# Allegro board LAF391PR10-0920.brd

Outline 301.1 x 113.1 mm; copper layers: TOP, GND1, IN1, GND2, IN2, IN3, VCC, IN4, GND3, BOTTOM. Coordinates in mm from the lower left corner of the outline.

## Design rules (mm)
net group BC: nets BC_CLK_ECE1117 BC_DAT_ECE1117
net group CPU_DP3_AUXN: nets CPU_DP3_AUXN CPU_DP3_AUXP
net group DP4: nets VCC_GT_SENSE VSS_GT_SENSE
net group DP5: nets VCCIO_SENSE VSSIO_SENSE
net group DP6: nets VCCSENSE VSSSENSE
net group PCIE_PRX_C_DTX_N4: nets PCIE_PRX_C_DTX_N4 PCIE_PRX_DTX_N4
net group PCIE_PRX_C_DTX_P4: nets PCIE_PRX_C_DTX_P4 PCIE_PRX_DTX_P4
net group PCIE_PTX_C_DRX_N4: nets PCIE_PTX_C_DRX_N4 PCIE_PTX_DRX_N4
net group PCIE_PTX_C_DRX_P4: nets PCIE_PTX_C_DRX_P4 PCIE_PTX_DRX_P4
net group PECI: nets PECI_EC PECI_EC_R
net group USB3_PRX_C_DTX_N1: nets USB3_PRX_C_DTX_N1 USB3_PRX_DTX_N1
net group USB3_PRX_C_DTX_P1: nets USB3_PRX_C_DTX_P1 USB3_PRX_DTX_P1
net group ASYNCHRONOUS: nets +DDR_VREF_A_CA +DDR_VREF_A_DQ +DDR_VREF_B_CA +DDR_VREF_B_DQ +DDR_VREF_CA CFG_RCOMP CPU_POPIRCOMP DDR_DRAMRST#_R EDP_COMP EDRAM_OPIO_RCOMP EMMC_RCOMP EOPIO_RCOMP H_CATERR# H_THERMTRIP# H_VCCST_PWRGD_XDP PCH_PLTRST# PCH_PLTRST#_5105 PCH_PLTRST#_AND PCH_PLTRST#_EC PCH_POPIRCOMP PCIE_RCOMPN PCIE_RCOMPP PLTRST_LAN# PLTRST_TPM# SD_RCOMP SM_RCOMP0 SM_RCOMP1 SM_RCOMP2 USBCOMP VCCST_PWRGD VCCST_PWRGD_CPU VCCST_PWRGD_EC XDP_OBS0 XDP_OBS0_R XDP_OBS1 XDP_OBS1_R XDP_OBS2_R XDP_OBS3_R
net group CARD READER: nets SD/MMCCD# SD/MMCCLK SD/MMCCLK_R SD/MMCCMD SD/MMCCMD_R SD/MMCDAT0/RCLK+ SD/MMCDAT0/RCLK+_R SD/MMCDAT1/RCLK- SD/MMCDAT1/RCLK-_R SD/MMCDAT2 SD/MMCDAT2_R SD/MMCDAT3 SD/MMCDAT3_R SD_UHS2_D0N SD_UHS2_D0P SD_UHS2_D1N SD_UHS2_D1P SDWP
net group CL_IAMT: nets PCH_CL_CLK1 PCH_CL_DATA1 PCH_CL_RST1#
net group CLK: nets CLKDET# CPU_XDP_TCLK DAT_TP_SIO_I2C_CLK JTAG_CLK MEC_XTAL1 MEC_XTAL2 MEC_XTAL2_R MSCLK PCH_JTAG_TCK PCI_CLK_LPC1 TBTA_ROM_CLK_PD_R UPD1_SMBCLK UPD1_SMBCLK_Q UPD2_SMBCLK XTALI XTALO XTALO_R
net group CODEC: nets +MIC2-VREFO-L +MIC2-VREFO-R AUD_HP_NB_SENSE AUD_HP_OUT_L AUD_HP_OUT_L1 AUD_HP_OUT_R AUD_HP_OUT_R1 AUD_SENSE_A HP_OUT_L HP_OUT_R INT_SPK_L+ INT_SPK_L- INT_SPK_R+ INT_SPK_R- INT_SPKR_L+ INT_SPKR_L- INT_SPKR_R+ INT_SPKR_R- RING2 RING2_R SLEEVE SLEEVE_R
net group CRITICAL: nets H_CPUPWRGD INTRUDER# PCH_DPWROK PCH_DPWROK_EC PCH_PCIE_WAKE# PCH_RSMRST# PCH_RSMRST#_AND PCH_RTCRST# PCIE_WAKE# PCIE_WAKE#_R RESET_OUT#_R SIO_PWRBTN# SIO_SLP_A# SRTCRST# SYS_PWROK SYS_RESET# SYS_RESET#_R XDP_DBRESET#
net group CRT: nets BLUE BLUE_CRT CLK_DDC2_CRT DAT_DDC2_CRT GREEN GREEN_CRT HSYNC_CONN HSYNC_CRT RED RED_CRT VSYNC_CONN VSYNC_CRT
net group DDR-DQS: nets DDR_A_DQS0 DDR_A_DQS1 DDR_A_DQS2 DDR_A_DQS3 DDR_A_DQS4 DDR_A_DQS5 DDR_A_DQS6 DDR_A_DQS7 DDR_A_DQS#0 DDR_A_DQS#1 DDR_A_DQS#2 DDR_A_DQS#3 DDR_A_DQS#4 DDR_A_DQS#5 DDR_A_DQS#6 DDR_A_DQS#7 DDR_B_DQS0 DDR_B_DQS1 DDR_B_DQS2 DDR_B_DQS3 DDR_B_DQS4 DDR_B_DQS5 DDR_B_DQS6 DDR_B_DQS7 DDR_B_DQS#0 DDR_B_DQS#1 DDR_B_DQS#2 DDR_B_DQS#3 DDR_B_DQS#4 DDR_B_DQS#5 DDR_B_DQS#6 DDR_B_DQS#7
net group DDRA-ALERT: nets DDR_A_ALERT#
net group DDRA-CKE: nets DDR_A_CKE0 DDR_A_CKE1 DDR_A_CKE2 DDR_A_CKE3
net group DDRA-CLK: nets DDR_A_CLK0 DDR_A_CLK1 DDR_A_CLK#0 DDR_A_CLK#1
net group DDRA-CTL: nets DDR_A_CS#0 DDR_A_CS#1 DDR_A_ODT0 DDR_A_ODT1
net group DDRA-D0: nets DDR_A_D0 DDR_A_D1 DDR_A_D2 DDR_A_D3 DDR_A_D4 DDR_A_D5 DDR_A_D6 DDR_A_D7
net group DDRA-D1: nets DDR_A_D8 DDR_A_D9 DDR_A_D10 DDR_A_D11 DDR_A_D12 DDR_A_D13 DDR_A_D14 DDR_A_D15
net group DDRA-D2: nets DDR_A_D16 DDR_A_D17 DDR_A_D18 DDR_A_D19 DDR_A_D20 DDR_A_D21 DDR_A_D22 DDR_A_D23
net group DDRA-D3: nets DDR_A_D24 DDR_A_D25 DDR_A_D26 DDR_A_D27 DDR_A_D28 DDR_A_D29 DDR_A_D30 DDR_A_D31
net group DDRA-D4: nets DDR_A_D32 DDR_A_D33 DDR_A_D34 DDR_A_D35 DDR_A_D36 DDR_A_D37 DDR_A_D38 DDR_A_D39
net group DDRA-D5: nets DDR_A_D40 DDR_A_D41 DDR_A_D42 DDR_A_D43 DDR_A_D44 DDR_A_D45 DDR_A_D46 DDR_A_D47
net group DDRA-D6: nets DDR_A_D48 DDR_A_D49 DDR_A_D50 DDR_A_D51 DDR_A_D52 DDR_A_D53 DDR_A_D54 DDR_A_D55
net group DDRA-D7: nets DDR_A_D56 DDR_A_D57 DDR_A_D58 DDR_A_D59 DDR_A_D60 DDR_A_D61 DDR_A_D62 DDR_A_D63
net group DDRA-MA: nets DDR_A_ACT# DDR_A_BA0 DDR_A_BA1 DDR_A_BG0 DDR_A_BG1 DDR_A_MA0 DDR_A_MA1 DDR_A_MA2 DDR_A_MA3 DDR_A_MA4 DDR_A_MA5 DDR_A_MA6 DDR_A_MA7 DDR_A_MA8 DDR_A_MA9 DDR_A_MA10 DDR_A_MA11 DDR_A_MA12 DDR_A_MA13 DDR_A_MA14 DDR_A_MA15 DDR_A_MA16 DDR_A_PARITY
net group DDRB-ALERT: nets DDR_B_ALERT#
net group DDRB-CKE: nets DDR_B_CKE0 DDR_B_CKE1 DDR_B_CKE2 DDR_B_CKE3
net group DDRB-CLK: nets DDR_B_CLK0 DDR_B_CLK1 DDR_B_CLK#0 DDR_B_CLK#1
net group DDRB-CTL: nets DDR_B_CS#0 DDR_B_CS#1 DDR_B_ODT0 DDR_B_ODT1
net group DDRB-D0: nets DDR_B_D0 DDR_B_D1 DDR_B_D2 DDR_B_D3 DDR_B_D4 DDR_B_D5 DDR_B_D6 DDR_B_D7
net group DDRB-D1: nets DDR_B_D8 DDR_B_D9 DDR_B_D10 DDR_B_D11 DDR_B_D12 DDR_B_D13 DDR_B_D14 DDR_B_D15
net group DDRB-D2: nets DDR_B_D16 DDR_B_D17 DDR_B_D18 DDR_B_D19 DDR_B_D20 DDR_B_D21 DDR_B_D22 DDR_B_D23
net group DDRB-D3: nets DDR_B_D24 DDR_B_D25 DDR_B_D26 DDR_B_D27 DDR_B_D28 DDR_B_D29 DDR_B_D30 DDR_B_D31
net group DDRB-D4: nets DDR_B_D32 DDR_B_D33 DDR_B_D34 DDR_B_D35 DDR_B_D36 DDR_B_D37 DDR_B_D38 DDR_B_D39
net group DDRB-D5: nets DDR_B_D40 DDR_B_D41 DDR_B_D42 DDR_B_D43 DDR_B_D44 DDR_B_D45 DDR_B_D46 DDR_B_D47
net group DDRB-D6: nets DDR_B_D48 DDR_B_D49 DDR_B_D50 DDR_B_D51 DDR_B_D52 DDR_B_D53 DDR_B_D54 DDR_B_D55
net group DDRB-D7: nets DDR_B_D56 DDR_B_D57 DDR_B_D58 DDR_B_D59 DDR_B_D60 DDR_B_D61 DDR_B_D62 DDR_B_D63
net group DDRB-MA: nets DDR_B_ACT# DDR_B_BA0 DDR_B_BA1 DDR_B_BG0 DDR_B_BG1 DDR_B_MA0 DDR_B_MA1 DDR_B_MA2 DDR_B_MA3 DDR_B_MA4 DDR_B_MA5 DDR_B_MA6 DDR_B_MA7 DDR_B_MA8 DDR_B_MA9 DDR_B_MA10 DDR_B_MA11 DDR_B_MA12 DDR_B_MA13 DDR_B_MA14 DDR_B_MA15 DDR_B_MA16 DDR_B_PARITY
net group DP: nets CPU_DP2_AUXN CPU_DP2_AUXN_C CPU_DP2_AUXP CPU_DP2_AUXP_C CPU_DP2_N0 CPU_DP2_N0_C CPU_DP2_N1 CPU_DP2_N1_C CPU_DP2_N2 CPU_DP2_N2_C CPU_DP2_N3 CPU_DP2_N3_C CPU_DP2_P0 CPU_DP2_P0_C CPU_DP2_P1 CPU_DP2_P1_C CPU_DP2_P2 CPU_DP2_P2_C CPU_DP2_P3 CPU_DP2_P3_C SW2_DP1_AUXN SW2_DP1_AUXN_C SW2_DP1_AUXP SW2_DP1_AUXP_C SW2_DP1_N0 SW2_DP1_N0_C SW2_DP1_N1 SW2_DP1_N1_C SW2_DP1_N2 SW2_DP1_N2_C SW2_DP1_N3 SW2_DP1_N3_C SW2_DP1_P0 SW2_DP1_P0_C SW2_DP1_P1 SW2_DP1_P1_C SW2_DP1_P2 SW2_DP1_P2_C SW2_DP1_P3 SW2_DP1_P3_C SW2_DP3_AUXN SW2_DP3_AUXN_C SW2_DP3_AUXP SW2_DP3_AUXP_C SW2_DP3_N0 SW2_DP3_N0_C SW2_DP3_N1 SW2_DP3_N1_C SW2_DP3_P0 SW2_DP3_P0_C SW2_DP3_P1 SW2_DP3_P1_C TBTA_AUXN_C
net group DP1.3: nets TBTA_RX1N TBTA_RX1P TBTA_RX2N TBTA_RX2P TBTA_SBU1 TBTA_SBU1_R TBTA_SBU2 TBTA_SBU2_R TBTA_TX1N TBTA_TX1N_C TBTA_TX1P TBTA_TX1P_C TBTA_TX2N TBTA_TX2N_C TBTA_TX2P TBTA_TX2P_C TUSB546A_SBU1_R TUSB546A_SBU2_R
net group EDP: nets EDP_AUXN EDP_AUXN_C EDP_AUXP EDP_AUXP_C EDP_TXN0 EDP_TXN0_C EDP_TXN1 EDP_TXN1_C EDP_TXP0 EDP_TXP0_C EDP_TXP1 EDP_TXP1_C
net group EMI: nets BIA_PWM BIA_PWM_EC BST_3V BST_5V CLKRUN# EDP_BIA_PWM HOST_DEBUG_TX M_ID2# TP_LAN_JTAG_TCK
net group ESD-GND: nets CPU_XDP_PRDY# CPU_XDP_PREQ# CPU_XDP_TDI CPU_XDP_TDO CPU_XDP_TMS CPU_XDP_TRST# PCH_JTAG_TDI PCH_JTAG_TDO PCH_JTAG_TMS PCH_PWROK POWER_SW#_MB POWER_SW_IN# TDI_XDP TDO_XDP TRST#_XDP XDP_JTAGX XDP_TMS
net group ESD-NOCROSS-MOAT: nets CFG0 CFG1 CFG2 CFG3 CFG4 CFG5 CFG6 CFG7 CFG8 CFG9 CFG10 CFG11 CFG12 CFG13 CFG14 CFG15 CFG16 CFG17 CFG18 CFG19 JTAG_RST# JTAG_TDI JTAG_TDO ME_SUS_PWR_ACK RUNPWROK SIO_EXT_SMI# SIO_SLP_S0# SIO_SLP_S3# SIO_SLP_S4# SIO_SLP_S5# SUSACK# USB_OC0# USB_OC1# USB_OC2# USB_OC3#
net group HDA: nets DMIC0 DMIC_CLK0 HDA_BIT_CLK HDA_BIT_CLK_R HDA_RST# HDA_SDIN0_R HDA_SDOUT HDA_SYNC
net group HDMI: nets CPU_DP1_AUXN CPU_DP1_AUXP CPU_DP1_CTRL_CLK CPU_DP1_CTRL_DATA CPU_DP1_N0 CPU_DP1_N1 CPU_DP1_N2 CPU_DP1_N3 CPU_DP1_P0 CPU_DP1_P1 CPU_DP1_P2 CPU_DP1_P3 HDMI_CLKN HDMI_CLKP HDMI_L_CLKN HDMI_L_CLKP HDMI_L_TX_N0 HDMI_L_TX_N1 HDMI_L_TX_N2 HDMI_L_TX_P0 HDMI_L_TX_P1 HDMI_L_TX_P2 HDMI_TX_N0 HDMI_TX_N1 HDMI_TX_N2 HDMI_TX_P0 HDMI_TX_P1 HDMI_TX_P2
net group I2C: nets ISH_I2C2_SCL ISH_I2C2_SCL_R ISH_I2C2_SDA ISH_I2C2_SDA_R
net group MDI: nets LAN_MDIN0 LAN_MDIN0_L LAN_MDIN1 LAN_MDIN1_L LAN_MDIN2 LAN_MDIN2_L LAN_MDIN3 LAN_MDIN3_L LAN_MDIP0 LAN_MDIP0_L LAN_MDIP1 LAN_MDIP1_L LAN_MDIP2 LAN_MDIP2_L LAN_MDIP3 LAN_MDIP3_L
net group MDI-CONN: nets RJ45_MDIN0 RJ45_MDIN1 RJ45_MDIN2 RJ45_MDIN3 RJ45_MDIP0 RJ45_MDIP1 RJ45_MDIP2 RJ45_MDIP3
net group OTHER-SINGLE: nets BAT1_LED# BAT2_LED# BATT_WHITE# BATT_YELLOW#
net group PCIE: nets PCIE_PRX_C_DTX_N1 PCIE_PRX_C_DTX_N11 PCIE_PRX_C_DTX_N12 PCIE_PRX_C_DTX_P1 PCIE_PRX_C_DTX_P11 PCIE_PRX_C_DTX_P12 PCIE_PRX_C_RD_DTX_N11 PCIE_PRX_C_RD_DTX_N12 PCIE_PRX_C_RD_DTX_P11 PCIE_PRX_C_RD_DTX_P12 PCIE_PRX_DTX_N1 PCIE_PRX_DTX_N3 PCIE_PRX_DTX_N11 PCIE_PRX_DTX_N12 PCIE_PRX_DTX_P1 PCIE_PRX_DTX_P3 PCIE_PRX_DTX_P11 PCIE_PRX_DTX_P12 PCIE_PRX_RD_DTX_N11 PCIE_PRX_RD_DTX_N12 PCIE_PRX_RD_DTX_P11 PCIE_PRX_RD_DTX_P12 PCIE_PTX_C_DRX_N1 PCIE_PTX_C_DRX_N3 PCIE_PTX_C_DRX_N11 PCIE_PTX_C_DRX_N12 PCIE_PTX_C_DRX_P1 PCIE_PTX_C_DRX_P3 PCIE_PTX_C_DRX_P11 PCIE_PTX_C_DRX_P12 PCIE_PTX_C_RD_DRX_N11 PCIE_PTX_C_RD_DRX_N12 PCIE_PTX_C_RD_DRX_P11 PCIE_PTX_C_RD_DRX_P12 PCIE_PTX_DRX_N1 PCIE_PTX_DRX_N3 PCIE_PTX_DRX_N11 PCIE_PTX_DRX_N12 PCIE_PTX_DRX_P1 PCIE_PTX_DRX_P3 PCIE_PTX_DRX_P11 PCIE_PTX_DRX_P12 PCIE_PTX_RD_DRX_N11 PCIE_PTX_RD_DRX_N12 PCIE_PTX_RD_DRX_P11 PCIE_PTX_RD_DRX_P12
net group PLATFORM CLK: nets CLK_ITPXDP_N CLK_ITPXDP_N_R CLK_ITPXDP_P CLK_ITPXDP_P_R CLK_PCIE_N0 CLK_PCIE_N1 CLK_PCIE_N3 CLK_PCIE_N4 CLK_PCIE_N5 CLK_PCIE_P0 CLK_PCIE_P1 CLK_PCIE_P3 CLK_PCIE_P4 CLK_PCIE_P5
net group PLATFORM CLK-S: nets CLKREQ_PCIE#0 CLKREQ_PCIE#1 CLKREQ_PCIE#3 CLKREQ_PCIE#4 CLKREQ_PCIE#5 ESPI_CLK ESPI_CLK_5105 SUSCLK XCLK_BIASREF
net group POWER-20: nets +1.0V_AMPHYPLL +1.0V_APLL +1.0V_APLLEBB +1.0V_PRIM_COREP +1.0V_VCCST_C +1.0V_VCCSTG_C +1.0V_VCCSTG_R +1.8VALWP +1VALWP +1VALWP_B+ +3.3V_ALWP +3.3V_LAN_OUT +3.3V_RUN_AUDIO_UZ5 +5V_ALWP +COINCELL +CRT_VCC +DC_IN_SS +DCIN_JACK +DV33_18 +PBATT +REGCTL_PNP10 +RSVD_VCC3P3_1 +RTC_CELL +RTC_CELL_VBAT +SDC_IN +SDREG2 +SIM_PWR +VCC_SFR_OC +VCHGR
net group POWERS: nets +1.0V_CLK1 +1.0V_CLK2 +1.0V_CLK3 +1.0V_CLK4 +1.0V_CLK5 +1.0V_PRIM_XDP +1.0V_SRAM +1.0V_VCCST +1.0V_VCCSTG +1.0VO_DSW +1.2V_LDO +1.8V_PGPPF +1.8V_RUN_UZ8 +2.5V_MEM +3.3V_1.8V_PGPPA +3.3V_1.8V_PGPPG +3.3V_ALW2 +3.3V_CAM +3.3V_HDD +3.3V_LAN_UZ2 +3.3V_PGPPD +3.3V_PGPPE +3.3V_RUN_AUDIO +3.3V_RUN_UZ3 +3.3V_SPI +3.3V_TP +3.3V_WLAN +3.3V_WLAN_UZ4 +3.3V_WWAN +5V_ALW2 +5V_RUN_AUDIO +5V_USB_CHG_PWR +EDP_VDD +GND_CHASSIS +LCDVDD +PECI_VREF +VDDA_AVDD1 +VHDMI_VCC +VR_CAP
net group RTC: nets PCH_RTCX1 PCH_RTCX2 PCH_RTCX2_R SUSCLK_R WIGIG_32KHZ
net group S-20: nets DDR_DRAMRST#
net group SATA0: nets SATA_PRX_C_DTX_N0 SATA_PRX_C_DTX_P0 SATA_PRX_C_RD_DTX_N0 SATA_PRX_C_RD_DTX_P0 SATA_PRX_DTX_N0 SATA_PRX_DTX_P0 SATA_PRX_RD_DTX_N0 SATA_PRX_RD_DTX_P0 SATA_PTX_C_DRX_N0 SATA_PTX_C_DRX_P0 SATA_PTX_C_RD_DRX_N0 SATA_PTX_C_RD_DRX_P0 SATA_PTX_DRX_N0 SATA_PTX_DRX_P0 SATA_PTX_RD_DRX_N0 SATA_PTX_RD_DRX_P0
net group SATA1B: nets PCIE_PRX_DTX_N8 PCIE_PRX_DTX_P8 PCIE_PTX_C_DRX_N8 PCIE_PTX_C_DRX_P8 PCIE_PTX_DRX_N8 PCIE_PTX_DRX_P8
net group SIM: nets UIM_CLK UIM_DATA UIM_RESET
net group SMB: nets CLK_TP_SIO_I2C_DAT CLK_TP_SIO_R CPU_DP2_CTRL_CLK CPU_DP2_CTRL_DATA DDR_XDP_WAN_SMBCLK DDR_XDP_WAN_SMBDAT HDMI_CTRL_CLK HDMI_CTRL_DATA ISPSCL ISPSDA MEM_SMBCLK MEM_SMBDATA PBAT_CHARGER_SMBCLK PBAT_CHARGER_SMBDAT PBAT_SMBCLK_C PBAT_SMBDAT_C SML0_SMBCLK SML0_SMBDATA SML1_SMBCLK SML1_SMBDATA USH_EXPANDER_SMBCLK USH_EXPANDER_SMBDAT
net group SPI: nets PCH_SPI_CLK PCH_SPI_CLK_0_R PCH_SPI_CLK_1_R PCH_SPI_CLK_2_R PCH_SPI_CLK_R1 PCH_SPI_CS#0 PCH_SPI_CS#0_R1 PCH_SPI_CS#0_R2 PCH_SPI_CS#1 PCH_SPI_CS#1_R1 PCH_SPI_CS#1_R2 PCH_SPI_CS#2 PCH_SPI_CS#2_R PCH_SPI_D0 PCH_SPI_D0_0_R PCH_SPI_D0_1_R PCH_SPI_D0_2_R PCH_SPI_D0_R1 PCH_SPI_D1 PCH_SPI_D1_0_R PCH_SPI_D1_1_R PCH_SPI_D1_2_R PCH_SPI_D1_R1 PCH_SPI_D2 PCH_SPI_D2_0_R PCH_SPI_D2_1_R PCH_SPI_D2_R1 PCH_SPI_D3 PCH_SPI_D3_0_R PCH_SPI_D3_1_R PCH_SPI_D3_R1 PCH_SPI_DO2_XDP PCH_SPI_DO_XDP TBTA_ROM_CLK_PD TBTA_ROM_CS#_PD TBTA_ROM_DI_PD TBTA_ROM_DO_PD
net group SVID: nets H_CPU_SVIDALRT#
net group SVID-5/15: nets VIDALERT_N VIDALERT_N_B VIDSCLK VIDSCLK_B VIDSOUT VIDSOUT_B
net group SW_USB20_N9: nets SW_USB20_N9 USB20_N9 USB20_N9_R
net group SW_USB20_P9: nets SW_USB20_P9 USB20_P9 USB20_P9_R
net group TBTA_AUX_C: nets TBTA_AUXP_C
net group THERMAL: nets REM_DIODE1_N REM_DIODE1_P REM_DIODE2_N REM_DIODE2_P REM_DIODE4_N REM_DIODE4_P
net group USB3.0: nets USB3_PRX_DTX_N2 USB3_PRX_DTX_N3 USB3_PRX_DTX_N6 USB3_PRX_DTX_P2 USB3_PRX_DTX_P3 USB3_PRX_DTX_P6 USB3_PRX_L_DTX_N2 USB3_PRX_L_DTX_P2 USB3_PTX_C_DRX_N1 USB3_PTX_C_DRX_N2 USB3_PTX_C_DRX_N3 USB3_PTX_C_DRX_N6 USB3_PTX_C_DRX_P1 USB3_PTX_C_DRX_P2 USB3_PTX_C_DRX_P3 USB3_PTX_C_DRX_P6 USB3_PTX_DRX_N1 USB3_PTX_DRX_N2 USB3_PTX_DRX_N3 USB3_PTX_DRX_N6 USB3_PTX_DRX_P1 USB3_PTX_DRX_P2 USB3_PTX_DRX_P3 USB3_PTX_DRX_P6 USB3_PTX_L_DRX_N2 USB3_PTX_L_DRX_P2
net group USB20: nets TBTA_BOT_N TBTA_BOT_N_R TBTA_BOT_P TBTA_BOT_P_R TBTA_TOP_N TBTA_TOP_N_R TBTA_TOP_P TBTA_TOP_P_R USB20_N1 USB20_N2 USB20_N2_R USB20_N4 USB20_N4_L USB20_N5 USB20_N5_R USB20_N7 USB20_N7_L USB20_N8 USB20_N8_R USB20_N10 USB20_P1 USB20_P2 USB20_P2_R USB20_P4 USB20_P4_L USB20_P5 USB20_P5_R USB20_P7 USB20_P7_L USB20_P8 USB20_P8_R USB20_P10
net group W6-S6: nets CORE_VID0 CORE_VID1 VSA_SEN+ VSA_SEN-
nets with their own width: min track width 0.254; nets +1.2V_MEM_CPUCLK EN_PD_HV_1# N16399089 N17185089 N17185092 N17370885 N17370921 N17370927 N17370961 N17370983 N17370999 N17371043 N17371125 N17371202 N35551576 N35551581 N35551713 N35551785 N35551806 N35551822 N36255106 PS_ID
nets with their own width: min track width 0.508; nets +1.0V_PRIM +3.3V_M_TPM +3.3V_RUN +UZ12_TPM GND N38749366
nets with their own width: min track width 0.762; nets +3.3V_VGA
nets with their own width: min track width 1.016; nets +0.6V_DDR_VTT
nets with their own width: min track width 2.286; nets +3.3V_HDD_M2

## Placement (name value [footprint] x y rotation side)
CA1  680P_0402_50V7K  [C_0402]  275.52 18.26 90 top
CA2  330P_0402_50V8J  [C_0402]  279.68 4.95 90 top
CA3  330P_0402_50V8J  [C_0402]  279.68 8.63 270 top
CA4  680P_0402_50V7K  [C_0402]  275.57 16.33 90 top
CA5  27P_0402_50V8J  [C_0402]  67.92 101.27 0 top
CA6  27P_0402_50V8J  [C_0402]  67.92 102.28 0 top
CA7  0.1U_0201_10V6K  [C_0201]  68.72 100.38 180 top
CA8  0.1U_0201_10V6K  [C_0201]  267.9 24.81 90 top
CA9  10U_0603_10V6M  [C_0603]  270.69 25.64 0 top
CA10  0.1U_0201_10V6K  [C_0201]  260.74 21.08 90 top
CA12  680P_0402_50V7K  [C_0402]  274.63 19.17 270 top
CA13  680P_0402_50V7K  [C_0402]  274.68 17.24 270 top
CA19  1000P_0402_50V7K  [C_0402]  261.05 25.95 180 top
CA22  1000P_0402_50V7K  [C_0402]  265.74 25.95 0 top
CA23  1000P_0402_50V7K  [C_0402]  263.81 25.83 0 top
CA24  1000P_0402_50V7K  [C_0402]  262.96 25.83 180 top
CA25  10U_0603_10V6M  [C_0603]  272.58 19.38 180 top
CA27  0.1U_0402_25V6  [C_0402]  274.46 22.35 90 top
CA28  0.1U_0402_25V6  [C_0402]  274.46 25.4 270 top
CA29  1U_0603_10V6K  [C_0603]  268.91 14.21 90 top
CA31  1U_0603_10V6K  [C_0603]  259.3 21.71 90 top
CA33  10P_0402_50V8J  [C_0402]  254.92 17.45 270 top
CA35  2.2U_0402_6.3V6M  [C_0402]  270.12 22.48 90 top
CA41  0.1U_0402_25V6  [C_0402]  260.33 23.34 270 top
CA43  10U_0603_10V6M  [C_0603]  271.26 21.76 0 top
CA44  10U_0603_10V6M  [C_0603]  271.26 20.57 0 top
CA45  0.1U_0201_10V6K  [C_0201]  266.38 25.85 0 bottom
CA46  10U_0603_10V6M  [C_0603]  258.45 28.41 90 top
CA47  0.1U_0201_10V6K  [C_0201]  261.46 26.34 180 bottom
CA48  10U_0603_10V6M  [C_0603]  258.59 26.06 180 top
CA49  1U_0603_10V6K  [C_0603]  272.72 19.16 270 bottom
CA51  10U_0603_10V6M  [C_0603]  272.47 23.92 180 top
CA52  10U_0603_10V6M  [C_0603]  275.07 16.56 180 bottom
CA53  10U_0603_10V6M  [C_0603]  260.28 18.78 270 top
CA54  10P_0402_50V8J  [C_0402]  258.13 19.83 180 top
CA55  0.1U_0201_10V6K  [C_0201]  263.8 15.29 0 top
CA56  10U_0603_10V6M  [C_0603]  263.33 14.46 270 top
CA57  0.1U_0201_10V6K  [C_0201]  266.84 15.16 0 top
CA58  10U_0603_10V6M  [C_0603]  266.44 14.08 0 top
CA59  10U_0603_10V6M  [C_0603]  255.71 31.8 90 top
CA60  0.1U_0201_10V6K  [C_0201]  256.72 32.51 90 top
CA61  10U_0603_10V6M  [C_0603]  254.31 22.59 270 top
CA62  100P_0402_50V8J  [C_0402]  275.39 21.54 270 top
CA63  12P_0402_50V8J  [C_0402]  254.59 32.23 90 top
CA64  68P_0402_50V8J  [C_0402]  253.67 32.23 90 top
CA65  12P_0402_50V8J  [C_0402]  267.39 11.91 90 top
CA66  68P_0402_50V8J  [C_0402]  266.5 11.91 90 top
CA67  12P_0402_50V8J  [C_0402]  241.02 34.72 180 top
CA68  68P_0402_50V8J  [C_0402]  241.02 33.83 180 top
CA69  33P_0402_50V8J  [C_0402]  266.07 15.16 180 top
CA70  0.1U_0402_25V6  [C_0402]  256.21 21.71 270 top
CA72  100P_0402_50V8J  [C_0402]  274.5 21.54 270 top
CA73  330P_0402_50V8J  [C_0402]  274.55 15.11 0 top
CA74  330P_0402_50V8J  [C_0402]  272.29 15.13 0 top
CC7  33P_0402_50V8J  [C_0402]  160.76 48.46 0 bottom
CC8  33P_0402_50V8J  [C_0402]  162.36 51.38 90 bottom
CC9  0.1U_0201_10V6K  [C_0201]  161.47 52.43 270 bottom
CC10  0.1U_0201_10V6K  [C_0201]  154.36 48.33 90 bottom
CC21  15P_0402_50V8J  [C_0402]  119.54 80.97 180 bottom
CC22  15P_0402_50V8J  [C_0402]  121.92 80.97 180 bottom
CC23  15P_0402_50V8J  [C_0402]  149.24 57.45 90 bottom
CC24  1U_0402_6.3V6K  [C_0402]  154.66 41.83 90 top
CC25  1U_0402_6.3V6K  [C_0402]  152 44.94 0 top
CC26  12P_0402_50V8J  [C_0402]  149.24 56.61 270 bottom
CC27  47P_0402_50V8J  [C_0402]  129.42 35.01 90 top
CC28  0.1U_0201_10V6K  [C_0201]  93.46 94.91 0 bottom
CC29  0.1U_0201_10V6K  [C_0201]  100.42 108.44 270 top
CC30  0.1U_0201_10V6K  [C_0201]  100.94 99.46 180 top
CC32  0.1U_0402_25V6  [C_0402]  83.88 99.44 270 bottom
CC33  0.1U_0402_25V6  [C_0402]  90.21 94.78 180 bottom
CC176  10U_0402_6.3V6M  [C_0402]  121.21 40.94 0 top
CC177  10U_0402_6.3V6M  [C_0402]  110.16 39.37 180 top
CC178  10U_0402_6.3V6M  [C_0402]  124.23 41.45 0 top
CC179  10U_0402_6.3V6M  [C_0402]  110.16 40.26 180 top
CC195  1U_0402_6.3V6K  [C_0402]  129.69 80.01 0 bottom
CC199  1U_0402_6.3V6K  [C_0402]  129.54 81.89 0 top
CC202  1U_0402_6.3V6K  [C_0402]  128.59 66.85 0 top
CC203  1U_0402_6.3V6K  [C_0402]  131.26 66.91 180 top
CC204  1U_0402_6.3V6K  [C_0402]  148.31 59.23 0 bottom
CC205  1U_0402_6.3V6K  [C_0402]  131.42 61.26 0 top
CC206  1U_0402_6.3V6K  [C_0402]  128.2 61.82 90 top
CC207  1U_0402_6.3V6K  [C_0402]  131.41 63.67 180 top
CC208  1U_0402_6.3V6K  [C_0402]  131 65.1 180 top
CC209  1U_0402_6.3V6K  [C_0402]  129.67 63.65 180 top
CC210  47U_0805_6.3V6M  [C_0805]  139.02 81.39 180 bottom
CC211  1U_0402_6.3V6K  [C_0402]  132.73 65.09 180 top
CC212  1U_0402_6.3V6K  [C_0402]  148.43 61.54 0 bottom
CC213  1U_0402_6.3V6K  [C_0402]  133.33 44.57 270 top
CC214  0.1U_0201_10V6K  [C_0201]  142.12 43.3 270 top
CC215  1U_0402_6.3V6K  [C_0402]  126.94 60.31 180 top
CC216  1U_0402_6.3V6K  [C_0402]  137.91 79.09 90 bottom
CC217  1U_0402_6.3V6K  [C_0402]  126.94 61.2 180 top
CC218  1U_0402_6.3V6K  [C_0402]  129.25 65.1 180 top
CC219  47U_0805_6.3V6M  [C_0805]  133.41 79.21 90 bottom
CC220  47U_0805_6.3V6M  [C_0805]  128.41 79.55 180 bottom
CC221  47U_0805_6.3V6M  [C_0805]  125.01 82.04 90 bottom
CC222  1U_0402_6.3V6K  [C_0402]  150.22 62.44 270 bottom
CC223  0.1U_0201_10V6K  [C_0201]  130.76 58.17 90 top
CC224  1U_0402_6.3V6K  [C_0402]  131.55 58.13 90 top
CC225  47U_0805_6.3V6M  [C_0805]  155.58 76.17 90 bottom
CC226  47U_0805_6.3V6M  [C_0805]  124.83 79.21 90 bottom
CC250  1U_0402_6.3V6K  [C_0402]  123.82 57.64 0 top
CC251  1U_0402_6.3V6K  [C_0402]  123.37 59.91 90 top
CC252  1U_0402_6.3V6K  [C_0402]  124.28 60.81 0 top
CC253  1U_0402_6.3V6K  [C_0402]  124.28 59.92 0 top
CC264  1U_0402_6.3V6K  [C_0402]  132.11 66.86 0 top
CC265  1U_0402_6.3V6K  [C_0402]  130.24 59.55 90 top
CC266  0.01UF_0402_25V7K  [C_0402]  144.71 37.89 0 top
CC269  0.1U_0402_25V6  [C_0402]  95.26 94.76 270 bottom
CC270  0.1U_0201_10V6K  [C_0201]  130.17 58.23 90 top
CC279  22U_0603_6.3V6M  [C_0603]  147.71 57.45 90 top
CC280  22U_0603_6.3V6M  [C_0603]  146.49 57.45 90 top
CC281  0.1U_0201_10V6K  [C_0201]  133.65 65.75 0 top
CC288  1U_0402_6.3V6K  [C_0402]  127 59.42 180 top
CC294  22U_0603_6.3V6M  [C_0603]  120.89 39.88 0 top
CC295  22U_0603_6.3V6M  [C_0603]  120.89 38.61 0 top
CC296  22U_0603_6.3V6M  [C_0603]  110.21 38.23 180 top
CC297  10U_0402_6.3V6M  [C_0402]  118.54 52.95 0 top
CC300  100P_0402_50V8J  [C_0402]  100 80.11 90 bottom
CC301  100P_0402_50V8J  [C_0402]  106.56 88.01 270 bottom
CC302  0.1U_0402_25V6  [C_0402]  145.36 86.69 0 bottom
CC303  0.1U_0402_25V6  [C_0402]  110.1 80.04 90 bottom
CC304  0.1U_0402_25V6  [C_0402]  108.03 80.23 90 top
CC305  0.1U_0402_25V6  [C_0402]  107.19 80.23 90 bottom
CC306  0.1U_0402_25V6  [C_0402]  83.89 104.92 180 bottom
CC307  0.1U_0402_25V6  [C_0402]  97.48 94.41 0 bottom
CC308  0.1U_0402_25V6  [C_0402]  105.34 102.36 0 top
CC310  0.1U_0402_25V6  [C_0402]  104.2 89.79 270 bottom
CC312  0.1U_0402_25V6  [C_0402]  110.37 84.68 90 bottom
CC313  0.1U_0201_10V6K  [C_0201]  129.4 59.93 90 top
CC314  0.1U_0201_10V6K  [C_0201]  133.44 64.72 0 top
CC316  33P_0402_50V8J  [C_0402]  143.21 43.2 270 top
CC318  33P_0402_50V8J  [C_0402]  154.39 62.92 90 bottom
CC319  33P_0402_50V8J  [C_0402]  149.39 65.49 180 bottom
CC320  33P_0402_50V8J  [C_0402]  154.26 65.69 180 top
CC321  33P_0402_50V8J  [C_0402]  104.32 77.26 90 top
CC322  2.2P_0402_50V8C  [C_0402]  126.75 52.37 180 top
CC323  2.2P_0402_50V8C  [C_0402]  133.15 63.67 180 top
CC324  2.2P_0402_50V8C  [C_0402]  129.43 58.77 180 top
CC325  2.2P_0402_50V8C  [C_0402]  133.72 79.88 270 top
CC326  1U_0402_6.3V6K  [C_0402]  133.52 62.34 270 top
CC331  2.2P_0402_50V8C  [C_0402]  130.38 36.8 0 top
CC332  2.2P_0402_50V8C  [C_0402]  133.41 36.25 90 top
CC333  2.2P_0402_50V8C  [C_0402]  134.27 36.27 90 top
CC334  12P_0402_50V8J  [C_0402]  147.69 81.75 0 bottom
CC335  12P_0402_50V8J  [C_0402]  146.81 81.75 180 bottom
CC340  0.1U_0402_25V6K  [C_0402]  250.5 41.87 180 top
CD1  10U_0603_10V6M  [C_0603]  82.64 20.83 270 top
CD2  10U_0603_10V6M  [C_0603]  92.17 20.83 270 top
CD3  10U_0603_10V6M  [C_0603]  79.85 11.18 90 top
CD4  10U_0603_10V6M  [C_0603]  82.39 11.18 90 top
CD5  10U_0603_10V6M  [C_0603]  78.58 11.18 90 top
CD6  10U_0603_10V6M  [C_0603]  84.67 11.05 90 top
CD7  10U_0603_10V6M  [C_0603]  88.66 11.38 90 top
CD8  10U_0603_10V6M  [C_0603]  107.02 11.31 90 top
CD9  1U_0402_6.3V6K  [C_0402]  81.57 20.48 270 top
CD10  1U_0402_6.3V6K  [C_0402]  91.02 20.45 270 top
CD11  1U_0402_6.3V6K  [C_0402]  89.72 20.44 270 top
CD12  1U_0402_6.3V6K  [C_0402]  77.43 11.31 90 top
CD13  1U_0402_6.3V6K  [C_0402]  75.58 20.48 270 top
CD14  1U_0402_6.3V6K  [C_0402]  89.85 11.51 90 top
CD15  1U_0402_6.3V6K  [C_0402]  85.82 11.43 90 top
CD16  1U_0402_6.3V6K  [C_0402]  101.31 20.45 270 top
CD17  330U_D3_2.5VY_R6M  [C_D3]  89.4 31.88 180 top
CD18  1U_0402_6.3V6K  [C_0402]  118.1 17.91 0 top
CD19  1U_0402_6.3V6K  [C_0402]  118.1 17.05 0 top
CD20  10U_0603_10V6M  [C_0603]  116.55 15.41 180 top
CD21  10U_0603_10V6M  [C_0603]  118.64 19.42 90 top
CD22  10U_0603_10V6M  [C_0603]  114.09 11.7 270 top
CD23  1U_0402_6.3V6K  [C_0402]  115.79 12.1 270 top
CD24  1U_0402_6.3V6K  [C_0402]  115.79 13.05 90 top
CD25  0.1U_0402_10V6K  [C_0402]  91.87 11.37 180 top
CD26  2.2U_0402_6.3V6M  [C_0402]  91.87 12.26 180 top
CD27  2.2U_0402_6.3V6M  [C_0402]  114.36 22.84 90 top
CD28  0.1U_0201_10V6K  [C_0201]  113.47 22.84 90 top
CD29  0.1U_0402_25V6  [C_0402]  51.17 14.06 90 top
CD31  0.022U_0402_16V7K  [C_0402]  94.22 12.27 270 top
CD32  0.1U_0201_10V6K  [C_0201]  49.53 26.67 180 top
CD33  10U_0603_10V6M  [C_0603]  182.46 20.83 270 top
CD34  10U_0603_10V6M  [C_0603]  173.14 21.07 270 top
CD35  10U_0603_10V6M  [C_0603]  171.67 11.18 90 top
CD36  10U_0603_10V6M  [C_0603]  162.4 11.18 90 top
CD37  10U_0603_10V6M  [C_0603]  151.1 20.66 270 top
CD38  10U_0603_10V6M  [C_0603]  146.01 11.31 90 top
CD39  10U_0603_10V6M  [C_0603]  164.81 11.31 90 top
CD40  10U_0603_10V6M  [C_0603]  168.71 21.07 270 top
CD41  1U_0402_6.3V6K  [C_0402]  189.07 11.31 90 top
CD42  1U_0402_6.3V6K  [C_0402]  171.92 20.45 270 top
CD43  1U_0402_6.3V6K  [C_0402]  167.57 20.57 270 top
CD44  1U_0402_6.3V6K  [C_0402]  155.28 11.31 90 top
CD45  1U_0402_6.3V6K  [C_0402]  158.99 11.51 90 top
CD46  1U_0402_6.3V6K  [C_0402]  135.04 11.2 180 top
CD47  1U_0402_6.3V6K  [C_0402]  192.59 19.43 270 top
CD48  1U_0402_6.3V6K  [C_0402]  183.61 20.58 270 top
CD49  330U_D3_2.5VY_R6M  [C_D3]  143.54 27.35 0 top
CD50  1U_0402_6.3V6K  [C_0402]  194.75 25.88 90 top
CD51  1U_0402_6.3V6K  [C_0402]  193.86 25.88 90 top
CD52  10U_0603_10V6M  [C_0603]  192.71 25.89 90 top
CD53  10U_0603_10V6M  [C_0603]  191.44 25.89 90 top
CD54  10U_0603_10V6M  [C_0603]  194.56 10.84 180 top
CD55  1U_0402_6.3V6K  [C_0402]  194.02 12.88 180 top
CD56  1U_0402_6.3V6K  [C_0402]  194.02 11.99 180 top
CD57  0.1U_0402_10V6K  [C_0402]  45.15 11.66 270 top
CD58  2.2U_0402_6.3V6M  [C_0402]  46.04 11.66 270 top
CD59  2.2U_0402_6.3V6M  [C_0402]  198.05 20.7 0 top
CD60  0.1U_0201_10V6K  [C_0201]  194.49 18.97 270 top
CD61  0.1U_0402_25V6  [C_0402]  142.05 11.41 180 top
CD62  0.022U_0402_16V7K  [C_0402]  45.52 14.83 90 top
CE3  2200P_0402_50V7K  [C_0402]  256.51 44.84 180 top
CE4  2200P_0402_50V7K  [C_0402]  254.31 52.24 180 top
CE8  .047U_0402_16V7K  [C_0402]  270.82 38.91 0 top
CE10  1U_0402_6.3V6K  [C_0402]  278.62 53.96 0 top
CE11  0.1U_0201_10V6K  [C_0201]  258.73 56.49 180 top
CE12  2.2U_0402_6.3V6M  [C_0402]  276.71 54.85 0 top
CE13  0.1U_0201_10V6K  [C_0201]  262.74 56.43 90 top
CE14  1U_0402_6.3V6K  [C_0402]  263.45 56.43 90 top
CE15  0.1U_0201_10V6K  [C_0201]  256.43 47.81 180 top
CE16  10U_0603_6.3V6M  [C_0603]  268.41 62.21 270 top
CE17  22U_0603_6.3V6M  [C_0603]  250.37 52.62 90 bottom
CE18  0.1U_0201_10V6K  [C_0201]  256.47 49.6 180 top
CE19  0.1U_0201_10V6K  [C_0201]  267.39 59.9 270 top
CE20  0.1U_0201_10V6K  [C_0201]  266.76 59.9 270 top
CE21  0.1U_0201_10V6K  [C_0201]  261.98 41.83 180 top
CE22  0.1U_0201_10V6K  [C_0201]  238.74 43.66 180 top
CE23  0.1U_0201_10V6K  [C_0201]  256.38 45.56 180 top
CE24  2200P_0402_50V7K  [C_0402]  265.21 56.52 180 top
CE25  0.1U_0201_10V6K  [C_0201]  277.04 49.41 0 top
CE26  2200P_0402_50V7K  [C_0402]  266.67 57.6 180 top
CE27  2200P_0402_50V7K  [C_0402]  268.03 56.35 180 top
CE28  10P_0402_50V8J  [C_0402]  258.83 57.45 180 top
CE29  10P_0402_50V8J  [C_0402]  259.69 57.45 0 top
CE30  1U_0402_6.3V6K  [C_0402]  274.01 50.83 0 top
CE31  1U_0402_6.3V6K  [C_0402]  269.04 57.32 270 top
CE32  10U_0603_6.3V6M  [C_0603]  180.78 89.77 90 bottom
CE35  100P_0402_50V8J  [C_0402]  109.21 58.52 270 top
CE36  0.1U_0402_25V6  [C_0402]  105.21 94.03 90 bottom
CE37  100P_0402_50V8J  [C_0402]  210.24 25.76 0 top
CE38  0.1U_0402_25V6  [C_0402]  272.98 62.78 180 top
CE39  100P_0402_50V8J  [C_0402]  90.05 80.98 270 bottom
CE40  4700P_0402_25V7K  [C_0402]  274.3 45.54 0 top
CE46  100P_0402_50V8J  [C_0402]  122.94 26.78 270 bottom
CE47  4700P_0402_25V7K  [C_0402]  277.72 45.35 180 top
CE52  0.1U_0402_25V6K  [C_0402]  277.68 41.13 90 top
CE53  0.1U_0402_25V6K  [C_0402]  276.86 37.26 180 top
CE54  10P_0402_50V8J  [C_0402]  256.51 51.29 180 top
CE57  33P_0402_50V8J  [C_0402]  254.69 36.75 90 top
CE59  12P_0402_50V8J  [C_0402]  241.74 49.32 90 top
CE60  68P_0402_50V8J  [C_0402]  240.85 49.32 90 top
CE61  68P_0402_50V8J  [C_0402]  277.6 44.12 0 top
CE62  4700P_0402_25V7K  [C_0402]  256.51 50.42 180 top
CE63  1U_0402_6.3V6K  [C_0402]  276.66 59.1 180 top
CE64  0.1U_0402_25V6  [C_0402]  261.5 61.96 0 top
CE65  22P_0402_50V8J  [C_0402]  257.31 61.92 180 top
CE66  0.1U_0402_25V6  [C_0402]  264.67 41.04 270 top
CI1  100U_1206_6.3V6M  [C_1206]  19.36 27.1 90 top
CI3  0.1U_0201_10V6K  [C_0201]  18.72 26.03 270 top
CI4  0.1U_0402_25V6  [C_0402]  21.26 23.21 90 bottom
CI5  0.1U_0402_25V6  [C_0402]  22.15 23.21 90 bottom
CI6  10U_0603_10V6M  [C_0603]  30.6 17.85 270 top
CI7  0.1U_0201_10V6K  [C_0201]  30.31 18.74 0 top
CI13  0.1U_0402_25V6  [C_0402]  282.31 27.72 90 bottom
CI14  100U_1206_6.3V6M  [C_1206]  281.49 19.99 90 bottom
CI16  0.1U_0402_25V6  [C_0402]  281.36 27.72 90 bottom
CI17  0.1U_0201_10V6K  [C_0201]  279.61 20.24 180 bottom
CI19  0.1U_0201_10V6K  [C_0201]  280.33 31.9 0 top
CI29  0.1U_0402_25V6  [C_0402]  251.77 33 180 bottom
CI30  0.1U_0402_25V6  [C_0402]  251.77 33.89 180 bottom
CI31  10U_0402_6.3V6M  [C_0402]  280.14 32.64 0 top
CI32  150U_B2_6.3VM_R35M  [C_B2]  280.93 21.64 0 top
CI33  47U_0603_6.3V6M  [C_0603]  280.09 33.7 0 top
CI34  47U_0603_6.3V6M  [C_0603]  280.09 34.95 0 top
CI43  12P_0402_50V8J  [C_0402]  279.7 27.71 0 top
CI44  68P_0402_50V8J  [C_0402]  279.7 28.6 0 top
CI45  12P_0402_50V8J  [C_0402]  25.53 18.78 180 top
CI46  68P_0402_50V8J  [C_0402]  25.53 19.8 180 top
CL1  0.1U_0402_25V6  [C_0402]  251.9 63.75 90 top
CL2  0.1U_0402_25V6  [C_0402]  252.91 63.75 90 top
CL3  0.1U_0201_10V6K  [C_0201]  264.72 70.11 90 top
CL4  10U_0603_10V6M  [C_0603]  265.87 68.94 270 top
CL5  0.1U_0402_25V6  [C_0402]  254.88 63.75 90 top
CL6  0.1U_0402_25V6  [C_0402]  255.9 63.75 90 top
CL7  0.1U_0201_10V6K  [C_0201]  252.4 74.47 180 top
CL8  0.1U_0201_10V6K  [C_0201]  255.3 77.81 90 bottom
CL9  0.1U_0201_10V6K  [C_0201]  260.53 77.9 90 top
CL10  0.1U_0201_10V6K  [C_0201]  251.49 67.97 180 top
CL11  0.1U_0201_10V6K  [C_0201]  259.03 67.99 0 top
CL12  22U_0603_6.3V6M  [C_0603]  258.94 67.04 270 top
CL13  27P_0402_50V8J  [C_0402]  263.12 73.58 0 top
CL14  27P_0402_50V8J  [C_0402]  262.13 73.58 180 top
CL15  0.1U_0201_10V6K  [C_0201]  272.03 63.55 0 top
CL16  0.1U_0201_10V6K  [C_0201]  258.72 86.03 0 top
CL17  0.1U_0201_10V6K  [C_0201]  258.72 88.95 0 top
CL18  470P_0402_50V7K  [C_0402]  280.47 86.28 90 top
CL19  0.1U_0201_10V6K  [C_0201]  281.49 70.02 270 top
CL20  0.1U_0201_10V6K  [C_0201]  258.72 91.99 0 top
CL21  0.1U_0201_10V6K  [C_0201]  258.72 95.04 0 top
CL22  10P_1808_3KV8J  [C_1808]  261.8 82.09 0 bottom
CL28  22U_0805_6.3V6M  [C_0805]  262.92 66.87 0 top
CL29  12P_0402_50V8J  [C_0402]  256.73 77.9 90 bottom
CL30  82P_0402_50V8J  [C_0402]  258.07 77.9 90 bottom
CMOS1  SHORT PADS~D  [SHORTPADS-NPM]  152.52 43.86 0 top
CN1  10U_0603_10V6M  [C_0603]  245.42 16.47 90 bottom
CN2  0.1U_0201_10V6K  [C_0201]  244.53 16.61 90 bottom
CN3  0.1U_0201_10V6K  [C_0201]  240.22 19.11 0 top
CN4  0.01UF_0402_25V7K  [C_0402]  228.08 15.21 90 top
CN5  0.01UF_0402_25V7K  [C_0402]  227.19 15.21 90 top
CN6  0.01UF_0402_25V7K  [C_0402]  224.4 15.21 90 top
CN7  0.01UF_0402_25V7K  [C_0402]  223.51 15.21 90 top
CN8  1000P_0402_50V7K  [C_0402]  245.8 7.84 90 top
CN9  0.1U_0201_10V6K  [C_0201]  246.69 7.96 90 top
CN10  0.1U_0201_10V6K  [C_0201]  246.6 9.6 180 top
CN11  0.1U_0201_10V6K  [C_0201]  246.6 10.23 180 top
CN12  0.01UF_0402_25V7K  [C_0402]  226.5 25.71 270 top
CN13  0.01UF_0402_25V7K  [C_0402]  225.61 25.71 270 top
CN14  0.01UF_0402_25V7K  [C_0402]  224.59 25.71 270 top
CN15  0.01UF_0402_25V7K  [C_0402]  223.7 25.71 270 top
CN16  0.01UF_0402_25V7K  [C_0402]  227.5 23.97 90 top
CN17  0.1U_0201_10V6K  [C_0201]  221.25 19.67 180 top
CN20  0.1U_0201_10V6K  [C_0201]  247.07 26.77 90 top
CN21  0.01UF_0402_25V7K  [C_0402]  249.13 19.99 270 top
CN22  0.22U_0402_10V6K  [C_0402]  242.69 26.21 0 top
CN23  0.22U_0402_10V6K  [C_0402]  242.69 25.32 0 top
CN26  0.22U_0402_10V6K  [C_0402]  243.39 22.65 0 top
CN27  0.22U_0402_10V6K  [C_0402]  243.39 23.54 0 top
CN30  0.1U_0201_10V6K  [C_0201]  232.25 24.46 180 top
CN31  0.01UF_0402_25V7K  [C_0402]  239.46 18.42 270 top
CN32  0.22U_0402_10V6K  [C_0402]  231.56 23.73 0 top
CN33  0.22U_0402_10V6K  [C_0402]  231.56 22.84 0 top
CN36  0.22U_0402_10V6K  [C_0402]  231.56 20.94 0 top
CN37  0.22U_0402_10V6K  [C_0402]  231.56 21.83 0 top
CN60  68P_0402_50V8J  [C_0402]  249.76 11.36 270 bottom
CN61  0.1U_0201_10V6K  [C_0201]  250.47 11.32 270 bottom
CN62  0.1U_0201_10V6K  [C_0201]  251.04 11.32 270 bottom
CN63  22U_0603_6.3V6M  [C_0603]  247.54 11.2 270 bottom
CN64  22U_0603_6.3V6M  [C_0603]  248.73 11.2 270 bottom
CN69  0.22U_0402_10V6K  [C_0402]  273.11 12.23 90 bottom
CN70  0.22U_0402_10V6K  [C_0402]  272.22 12.23 90 bottom
CN71  0.22U_0402_10V6K  [C_0402]  258.45 9.93 180 bottom
CN72  0.22U_0402_10V6K  [C_0402]  258.45 10.82 180 bottom
CR1  4.7U_0402_6.3V6M  [C_0402]  81.79 94.2 180 top
CR2  0.1U_0201_10V6K  [C_0201]  83.11 94.75 90 bottom
CR3  0.1U_0201_10V6K  [C_0201]  75.87 92.63 270 bottom
CR4  10U_0402_6.3V6M  [C_0402]  75.11 92.76 270 bottom
CR5  4.7U_0603_6.3V6K  [C_0603]  75.45 95.98 180 bottom
CR6  0.1U_0201_10V6K  [C_0201]  75.49 95.02 180 bottom
CR7  0.1U_0201_10V6K  [C_0201]  75.87 91.11 180 bottom
CR11  0.1U_0402_25V6  [C_0402]  80.53 88.87 90 bottom
CR12  0.1U_0402_25V6  [C_0402]  79.64 88.87 90 bottom
CR13  0.1U_0402_25V6  [C_0402]  78.5 88.87 90 bottom
CR14  0.1U_0402_25V6  [C_0402]  77.61 88.87 90 bottom
CR15  1U_0402_6.3V6K  [C_0402]  81.67 98.52 90 bottom
CR17  0.1U_0201_10V6K  [C_0201]  87.27 96 0 top
CR18  4.7U_0603_6.3V6K  [C_0603]  86.8 95.11 0 top
CR19  0.1U_0201_10V6K  [C_0201]  84.08 110.46 0 bottom
CR20  4.7U_0603_6.3V6K  [C_0603]  83.62 109.52 0 bottom
CR21  5P_0402_50V8C  [C_0402]  76.31 99.44 270 bottom
CR22  1U_0402_6.3V6K  [C_0402]  78.12 98.52 90 bottom
CR25  12P_0402_50V8J  [C_0402]  76.38 87.6 270 top
CR26  82P_0402_50V8J  [C_0402]  77.27 87.6 270 top
CR27  12P_0402_50V8J  [C_0402]  83.88 94.71 90 bottom
CR28  82P_0402_50V8J  [C_0402]  84.76 94.71 90 bottom
CT70  .1U_0402_16V7K  [C_0402]  45.42 69.9 180 bottom
CT71  2.2U_0402_16V6K  [C_0402]  28.34 66.37 90 top
CT72  2.2U_0402_16V6K  [C_0402]  31.63 64.03 0 top
CT73  2.2U_0402_16V6K  [C_0402]  22.1 66.05 180 top
CT74  1U_0402_16V6K  [C_0402]  25.29 66.88 90 top
CT75  22U_0805_25V6M  [C_0805]  28.8 51.41 270 bottom
CT76  22U_0805_25V6M  [C_0805]  30.57 51.41 270 bottom
CT77  22U_0805_25V6M  [C_0805]  25.29 51.41 270 bottom
CT78  22U_0805_25V6M  [C_0805]  27.07 51.41 270 bottom
CT80  0.1U_0201_10V6K  [C_0201]  22.71 67.69 270 top
CT81  0.1U_0201_10V6K  [C_0201]  22.08 67.69 270 top
CT82  1U_0603_25V6K  [C_0603]  25.65 56.89 180 top
CT83  1U_0402_16V6K  [C_0402]  24.4 66.88 90 top
CT84  10U_0603_6.3V6M  [C_0603]  27.26 66.38 90 top
CT85  820P_0402_50V7K  [C_0402]  21.65 57.15 270 top
CT86  820P_0402_50V7K  [C_0402]  21.65 58.92 270 top
CT87  0.22U_0402_16V7K  [C_0402]  22.57 59.84 180 top
CT88  0.1U_0201_10V6K  [C_0201]  16.41 63.8 180 top
CT89  1U_0402_10V6K  [C_0402]  17.38 63.67 0 top
CT90  1U_0402_10V6K  [C_0402]  19.51 66.8 270 top
CT91  2.2U_0402_10V6M  [C_0402]  12.79 65.27 270 top
CT92  0.1U_0402_25V6K  [C_0402]  13.9 65.27 270 top
CT93  1U_0402_10V6K  [C_0402]  16.23 55.55 0 top
CT94  1U_0603_50V6K  [C_0603]  11.42 58.09 0 top
CT95  0.22U_0201_6.3V6K  [C_0201]  14.19 69.84 180 bottom
CT96  0.22U_0201_6.3V6K  [C_0201]  14.19 70.47 180 bottom
CT97  0.22U_0201_6.3V6K  [C_0201]  12.89 75.84 180 top
CT98  0.22U_0201_6.3V6K  [C_0201]  12.89 75.21 180 top
CT99  0.01U_0201_25V6K  [C_0201]  8.87 73.08 90 top
CT100  0.01U_0201_25V6K  [C_0201]  8.3 73.08 90 top
CT101  0.01U_0201_25V6K  [C_0201]  7.93 69.96 270 top
CT102  0.01U_0201_25V6K  [C_0201]  8.51 69.96 270 top
CT103  0.1U_0402_25V6  [C_0402]  32.96 73.25 180 top
CT104  0.1U_0402_25V6  [C_0402]  32.96 74.14 180 top
CT105  0.1U_0402_25V6  [C_0402]  33.05 75.26 180 top
CT106  0.1U_0402_25V6  [C_0402]  33.05 76.15 180 top
CT107  0.1U_0402_25V6  [C_0402]  33.15 77.01 180 top
CT108  0.1U_0402_25V6  [C_0402]  33.15 77.9 180 top
CT109  0.1U_0402_25V6  [C_0402]  33.15 78.79 180 top
CT110  0.1U_0402_25V6  [C_0402]  33.15 79.68 180 top
CT111  0.1U_0402_25V6  [C_0402]  27.49 69.69 90 top
CT112  0.1U_0402_25V6  [C_0402]  26.6 69.69 90 top
CT113  0.1U_0402_25V6  [C_0402]  32.64 72.36 180 top
CT114  0.1U_0402_25V6  [C_0402]  32.64 71.47 180 top
CT115  0.1U_0402_25V6  [C_0402]  29.39 81.23 270 top
CT116  0.1U_0402_25V6  [C_0402]  28.5 81.23 270 top
CT117  10U_0402_6.3V6M  [C_0402]  24.31 80.46 90 top
CT118  0.1U_0201_10V6K  [C_0201]  25.07 80.5 90 top
CT119  0.1U_0201_10V6K  [C_0201]  28.47 70.02 0 top
CT120  0.1U_0201_10V6K  [C_0201]  31.02 80.39 90 top
CT121  0.1U_0201_10V6K  [C_0201]  28.47 70.66 0 top
CT122  2.2U_0402_6.3V6M  [C_0402]  25.46 70.61 270 top
CT189  12P_0402_50V8J  [C_0402]  10.62 72.74 90 top
CT190  82P_0402_50V8J  [C_0402]  9.25 69.85 270 top
CT213  0.1U_0402_25V6  [C_0402]  32.87 78.91 0 bottom
CV1  0.1U_0402_25V6  [C_0402]  72.45 94.03 180 bottom
CV2  0.1U_0402_25V6  [C_0402]  72.45 93.14 180 bottom
CV3  0.1U_0402_25V6  [C_0402]  72.45 92.25 180 bottom
CV4  0.1U_0402_25V6  [C_0402]  72.45 91.36 180 bottom
CV5  0.1U_0402_25V6  [C_0402]  72.5 90.47 180 bottom
CV6  0.1U_0402_25V6  [C_0402]  72.5 89.58 180 bottom
CV11  0.1U_0603_50V7K  [C_0603]  69.46 96.52 180 top
CV12  0.1U_0201_10V6K  [C_0201]  68.55 91.11 0 top
CV13  1000P_0402_50V7K  [C_0402]  79.2 100.68 90 top
CV14  0.01U_0402_50V7K  [C_0402]  79.2 99.69 270 top
CV15  0.1U_0603_50V7K  [C_0603]  75.62 102.92 180 top
CV16  10U_0603_10V6M  [C_0603]  69.99 88.31 0 top
CV17  0.01UF_0402_25V7K  [C_0402]  73.77 90.98 90 top
CV18  12P_0402_50V8J  [C_0402]  65.03 106.54 180 top
CV19  82P_0402_50V8J  [C_0402]  65.03 107.43 180 top
CV20  12P_0402_50V8J  [C_0402]  68.3 90.34 0 top
CV21  82P_0402_50V8J  [C_0402]  68.3 89.45 0 top
CV22  12P_0402_50V8J  [C_0402]  65.66 99.74 180 top
CV23  82P_0402_50V8J  [C_0402]  65.66 98.85 180 top
CV24  12P_0402_50V8J  [C_0402]  69.09 98.47 180 top
CV25  82P_0402_50V8J  [C_0402]  69.09 97.58 180 top
CV31  0.1U_0402_25V6  [C_0402]  20.64 42.85 180 bottom
CV32  0.1U_0402_25V6  [C_0402]  20.64 43.73 180 bottom
CV33  0.1U_0402_25V6  [C_0402]  20.64 46.47 180 bottom
CV34  0.1U_0402_25V6  [C_0402]  20.64 47.35 180 bottom
CV35  0.1U_0402_25V6  [C_0402]  20.64 44.69 180 bottom
CV36  0.1U_0402_25V6  [C_0402]  20.64 45.58 180 bottom
CV37  0.1U_0402_25V6  [C_0402]  19.73 48.24 0 bottom
CV38  0.1U_0402_25V6  [C_0402]  19.73 49.13 0 bottom
CV39  0.1U_0201_10V6K  [C_0201]  18.72 52.33 90 bottom
CV40  0.1U_0201_10V6K  [C_0201]  15.83 54.56 0 bottom
CV41  10U_0603_10V6M  [C_0603]  15.83 53.67 0 bottom
CV81  0.01UF_0402_25V7K  [C_0402]  160.15 87.17 180 top
CV82  0.01UF_0402_25V7K  [C_0402]  172.7 85.26 0 top
CV83  0.1U_0201_10V6K  [C_0201]  172.86 80.59 0 top
CV84  0.1U_0201_10V6K  [C_0201]  160.11 82.55 180 top
CV85  0.1U_0201_10V6K  [C_0201]  163.82 78.89 270 top
CV86  0.1U_0201_10V6K  [C_0201]  164.39 78.3 90 top
CV87  0.1U_0201_10V6K  [C_0201]  164.96 78.3 90 top
CV88  0.1U_0201_10V6K  [C_0201]  165.9 78.3 90 top
CV89  0.1U_0201_10V6K  [C_0201]  166.48 78.3 90 top
CV90  0.1U_0201_10V6K  [C_0201]  167.06 78.3 90 top
CV91  0.1U_0201_10V6K  [C_0201]  167.63 78.3 90 top
CV92  0.1U_0201_10V6K  [C_0201]  168.5 78.3 90 top
CV93  0.1U_0201_10V6K  [C_0201]  169.07 78.3 90 top
CV94  0.1U_0201_10V6K  [C_0201]  173.45 82.47 180 top
CV95  0.1U_0201_10V6K  [C_0201]  173.45 83.04 180 top
CV96  2.2U_0402_6.3V6M  [C_0402]  169.78 78.86 270 top
CV100  0.1U_0402_25V6  [C_0402]  288.09 48.76 0 top
CV101  0.1U_0402_25V6  [C_0402]  288.09 51.48 0 top
CV102  4.7U_0402_6.3V6M  [C_0402]  288.09 50.59 0 top
CV103  0.1U_0402_25V6  [C_0402]  283.39 44.57 270 top
CV104  0.1U_0402_25V6  [C_0402]  279.9 51.14 180 top
CV105  2.2U_0402_16V6K  [C_0402]  279.9 52.03 180 top
CV106  0.1U_0402_25V6  [C_0402]  279.91 50.21 180 top
CV107  0.1U_0402_10V7K  [C_0402]  284.28 43.66 90 top
CV108  0.1U_0402_10V7K  [C_0402]  285.17 43.66 90 top
CV109  0.1U_0402_10V7K  [C_0402]  286.06 43.66 90 top
CV110  0.1U_0402_10V7K  [C_0402]  286.95 43.66 90 top
CV111  0.1U_0402_10V7K  [C_0402]  281.23 43.66 90 top
CV112  0.1U_0402_10V7K  [C_0402]  282.12 43.66 90 top
CV126  12P_0402_50V8J  [C_0402]  283.01 60.73 90 top
CV127  12P_0402_50V8J  [C_0402]  283.01 59.61 270 top
CV128  12P_0402_50V8J  [C_0402]  283.01 56.41 90 top
CV129  3.3P_0402_50V8C  [C_0402]  285.04 60.75 90 top
CV130  3.3P_0402_50V8C  [C_0402]  285.04 58.59 90 top
CV131  3.3P_0402_50V8C  [C_0402]  285.04 57.29 270 top
CV132  2P_0402_50V8C~D  [C_0402]  288.85 52.37 0 top
CV133  2P_0402_50V8C~D  [C_0402]  288.85 53.64 0 top
CV134  1U_0402_6.3V6K  [C_0402]  288.98 50.08 180 bottom
CV135  0.1U_0402_16V4Z  [C_0402]  288.98 49.65 180 top
CV635  0.1U_0402_25V6K  [C_0402]  65.04 110.45 180 top
CZ1  0.1U_0201_10V6K  [C_0201]  65.63 100.5 180 top
CZ2  0.1U_0201_10V6K  [C_0201]  64.9 105.77 180 top
CZ3  100P_0402_50V8J  [C_0402]  50.68 96.44 180 top
CZ10  0.1U_0402_25V6  [C_0402]  270.06 29.64 270 top
CZ11  0.1U_0402_25V6  [C_0402]  270.94 29.64 270 top
CZ12  0.1U_0402_25V6  [C_0402]  205.91 31.12 0 bottom
CZ13  0.1U_0402_25V6  [C_0402]  205.91 30.11 0 bottom
CZ17  .047U_0402_16V7K  [C_0402]  258.5 38.77 90 bottom
CZ18  .047U_0402_16V7K  [C_0402]  259.39 38.77 90 bottom
CZ19  33P_0402_50V8J  [C_0402]  278.24 36.57 270 top
CZ20  22U_0603_6.3V6M  [C_0603]  278.69 37.58 90 top
CZ21  33P_0402_50V8J  [C_0402]  279.1 36.57 270 top
CZ23  47P_0402_50V8J  [C_0402]  250.5 41.96 270 bottom
CZ24  100P_0402_50V8J  [C_0402]  248.72 41.96 270 bottom
CZ25  2000P_0402_50V7K  [C_0402]  249.61 41.96 270 bottom
CZ26  100U_B2_6.3VM_R35M  [C_B2]  250.19 43.88 270 bottom
CZ27  10U_0603_10V6M  [C_0603]  216.22 38.01 270 top
CZ28  0.01UF_0402_25V7K  [C_0402]  215.12 37.72 270 top
CZ29  0.01UF_0402_25V7K  [C_0402]  218.24 20.09 180 top
CZ30  0.1U_0201_10V6K  [C_0201]  218.03 20.8 180 top
CZ31  0.1U_0201_10V6K  [C_0201]  218.03 21.36 180 top
CZ32  4.7U_0603_6.3V6K  [C_0603]  214.01 37.8 270 top
CZ33  15P_0402_50V8J  [C_0402]  218.27 19.22 180 top
CZ34  15P_0402_50V8J  [C_0402]  218.24 18.33 180 top
CZ35  15P_0402_50V8J  [C_0402]  217.3 37.65 270 top
CZ36  15P_0402_50V8J  [C_0402]  218.22 37.65 270 top
CZ37  4.7U_0402_6.3V6M  [C_0402]  112.1 97.14 180 top
CZ38  47P_0402_50V8J  [C_0402]  117.18 97.14 180 top
CZ39  33P_0402_50V8J  [C_0402]  117.78 109.47 270 top
CZ40  33P_0402_50V8J  [C_0402]  114.64 97.14 90 top
CZ41  0.1U_0402_25V6  [C_0402]  112.1 98.03 180 top
CZ50  0.1U_0201_10V6K  [C_0201]  159.03 56.04 180 top
CZ51  0.1U_0201_10V6K  [C_0201]  153.73 57.79 90 top
CZ52  10U_0603_10V6M  [C_0603]  153.59 56.92 270 top
CZ53  0.1U_0201_10V6K  [C_0201]  156.05 63.8 180 top
CZ54  0.1U_0201_10V6K  [C_0201]  161.35 61.22 90 top
CZ55  10U_0603_10V6M  [C_0603]  164.08 62.02 180 top
CZ56  0.1U_0402_25V6  [C_0402]  167.05 65.85 270 top
CZ57  12P_0402_50V8J  [C_0402]  155.52 55.67 270 top
CZ58  68P_0402_50V8J  [C_0402]  154.64 55.67 270 top
CZ59  12P_0402_50V8J  [C_0402]  165.08 61.9 0 top
CZ60  68P_0402_50V8J  [C_0402]  155.83 64.56 180 top
CZ61  .047U_0402_16V7K  [C_0402]  251.75 11.34 270 bottom
CZ62  68P_0402_50V8J  [C_0402]  259.52 12.09 0 top
CZ63  68P_0402_50V8J  [C_0402]  258.7 12.09 180 top
CZ64  0.1U_0201_10V6K  [C_0201]  255.21 11.86 180 top
CZ66  0.1U_0201_10V6K  [C_0201]  270.02 11.86 0 top
CZ67  0.1U_0201_10V6K  [C_0201]  254.08 13.31 90 top
CZ68  0.1U_0201_10V6K  [C_0201]  255.92 13.39 90 top
CZ69  68P_0402_50V8J  [C_0402]  255.12 13.03 90 top
CZ71  68P_0402_50V8J  [C_0402]  269.98 12.62 0 top
CZ72  68P_0402_50V8J  [C_0402]  253.88 11.98 180 top
CZ73  68P_0402_50V8J  [C_0402]  256.04 12.09 0 top
CZ75  10U_0402_6.3V6M  [C_0402]  159.11 55.22 180 top
CZ80  10P_0402_50V8J  [C_0402]  202.57 28.09 180 top
CZ81  10P_0402_50V8J  [C_0402]  203.69 28.09 0 top
CZ82  0.1U_0201_10V6K  [C_0201]  205.41 36.24 0 top
CZ83  68P_0402_50V8J  [C_0402]  199.52 24.61 0 top
CZ84  68P_0402_50V8J  [C_0402]  199.57 23.16 270 top
CZ85  68P_0402_50V8J  [C_0402]  200.49 22.27 90 top
CZ86  68P_0402_50V8J  [C_0402]  201.38 22.27 90 top
CZ87  68P_0402_50V8J  [C_0402]  202.29 22.27 90 top
CZ88  68P_0402_50V8J  [C_0402]  203.23 20.82 90 top
CZ89  68P_0402_50V8J  [C_0402]  204.17 20.82 90 top
CZ90  0.1U_0201_10V6K  [C_0201]  204.78 20.24 90 bottom
CZ91  0.1U_0201_10V6K  [C_0201]  200.97 20.62 90 top
CZ92  0.1U_0201_10V6K  [C_0201]  200.36 20.62 90 top
CZ93  0.1U_0201_10V6K  [C_0201]  278.73 71.48 180 top
CZ100  1U_0402_6.3V6K  [C_0402]  131.32 85.06 180 bottom
CZ101  0.1U_0201_10V6K  [C_0201]  131.75 81.33 270 bottom
CZ102  1U_0402_6.3V6K  [C_0402]  124.23 40.5 0 top
CZ103  0.1U_0201_10V6K  [C_0201]  127.54 38.6 0 top
CZ104  0.1U_0402_10V7K  [C_0402]  154.23 29.71 270 top
CZ105  1U_0402_6.3V6K  [C_0402]  136.12 89.84 90 bottom
CZ106  0.1U_0201_10V6K  [C_0201]  131.04 88.21 270 bottom
CZ109  470P_0402_50V7K  [C_0402]  231.3 44.22 90 top
CZ110  470P_0402_50V7K  [C_0402]  232.62 43.73 90 top
CZ111  0.1U_0201_10V6K  [C_0201]  234.37 41.74 270 top
CZ112  0.1U_0201_10V6K  [C_0201]  173.14 60.02 180 top
CZ113  470P_0402_50V7K  [C_0402]  173.05 60.78 180 top
CZ114  1000P_0402_50V7K  [C_0402]  172.66 62.47 180 top
CZ115  0.1U_0201_10V6K  [C_0201]  173.27 63.22 180 top
CZ116  0.1U_0201_10V6K  [C_0201]  210.79 31.92 180 top
CZ117  470P_0402_50V7K  [C_0402]  210.7 32.69 180 top
CZ118  470P_0402_50V7K  [C_0402]  210.7 34.08 180 top
CZ119  0.1U_0201_10V6K  [C_0201]  230.56 43.7 90 top
CZ120  0.1U_0201_10V6K  [C_0201]  237.93 36.62 0 top
CZ121  470P_0402_50V7K  [C_0402]  234.5 35.23 90 top
CZ122  0.1U_0201_10V6K  [C_0201]  210.56 34.97 180 top
CZ124  2200P_0402_50V7K  [C_0402]  229.8 43.53 90 top
CZ125  0.1U_0201_10V6K  [C_0201]  247.71 35.89 90 top
CZ126  220P_0402_50V7K  [C_0402]  246.44 34.34 0 top
CZ127  1000P_0402_50V7K  [C_0402]  246.44 33.45 0 top
CZ128  0.1U_0201_10V6K  [C_0201]  244.53 34.34 270 top
CZ129  0.1U_0201_10V6K  [C_0201]  242.07 11.35 180 top
CZ130  470P_0402_50V7K  [C_0402]  240.59 10.84 180 top
CZ197  470P_0402_50V7K  [C_0402]  236.55 41.07 90 top
CZ198  100P_0402_50V8J  [C_0402]  261.14 38.76 0 bottom
CZ200  0.1U_0402_25V6K  [C_0402]  63.39 101.39 180 top
DA1  AZ5123-02S.R7G_SOT23-3  [L03ESDL5V0CC3-2_SOT23-3]  283.42 7.01 90 top
DA2  PESD5V0U2BT_SOT23-3  [L03ESDL5V0CC3-2_SOT23-3]  281.36 2.97 270 top
DA3  AZ5123-02S.R7G_SOT23-3  [L03ESDL5V0CC3-2_SOT23-3]  283.47 10.87 90 top
DA6  PESD5V0U2BT_SOT23-3  [L03ESDL5V0CC3-2_SOT23-3]  252.02 19.66 90 bottom
DA7  PESD5V0U2BT_SOT23-3  [L03ESDL5V0CC3-2_SOT23-3]  252.02 15.77 90 bottom
DA8  -  [RB751S40T1G_SOD523-2]  256.15 24.96 270 top
DC1  RB751S40T1G_SOD523-2  [RB520SM-30T2R_EMD2-2]  252.49 39.29 180 top
DC2  RB751S40T1G_SOD523-2  [RB520SM-30T2R_EMD2-2]  201.22 35.82 270 top
DE1  BZV55-B5V6_SOD80C2  [BZV55-B5V1_SOD80C2]  182.38 89.63 90 bottom
DE2  RB751S40T1G_SOD523-2  [RB520SM-30T2R_EMD2-2]  259.1 60.88 180 top
DI1  -  [L05ESDL5V0NA-4_SLP2510P8-10-9]  19.81 20.26 270 bottom
DI2  -  [AZC199-02SPR7G_SOT23-3]  20.6 21.23 270 top
DI4  -  [L05ESDL5V0NA-4_SLP2510P8-10-9]  282.24 26.32 90 bottom
DI5  -  [AZC199-02SPR7G_SOT23-3]  280.7 25.22 90 top
DT1  1N4148WS-L_SOD323-2  [1N4148WS-7-F_SOD323-2]  18.03 61.25 270 top
DT2  1N4148WS-L_SOD323-2  [1N4148WS-7-F_SOD323-2]  16.31 61.25 270 top
DT3  1N4148WS-L_SOD323-2  [1N4148WS-7-F_SOD323-2]  18.27 56.88 180 top
DT4  -  [L30ESD24VC3-2_SOT23-3]  13.07 81.48 0 bottom
DT5  AZ5B75-01B_CSP0603P2Y  [ESD8011MUT5G_X3DFN2-2-S]  12.93 69.82 270 bottom
DT6  AZ5B75-01B_CSP0603P2Y  [ESD8011MUT5G_X3DFN2-2-S]  12.93 70.48 90 bottom
DT9  AZ5B75-01B_CSP0603P2Y  [ESD8011MUT5G_X3DFN2-2-S]  11.59 75.17 270 bottom
DT10  AZ5B75-01B_CSP0603P2Y  [ESD8011MUT5G_X3DFN2-2-S]  11.59 75.88 90 bottom
DT13  AZ5B75-01B_CSP0603P2Y  [ESD8011MUT5G_X3DFN2-2-S]  10.9 67.79 270 top
DT14  AZ5B75-01B_CSP0603P2Y  [ESD8011MUT5G_X3DFN2-2-S]  10.9 68.45 90 top
DT17  AZ5B75-01B_CSP0603P2Y  [ESD8011MUT5G_X3DFN2-2-S]  11.59 75.88 90 top
DT18  AZ5B75-01B_CSP0603P2Y  [ESD8011MUT5G_X3DFN2-2-S]  11.59 75.17 270 top
DT39  -  [L05ESDL5V0NA-4_SLP2510P8-10-9]  11.56 71.82 270 bottom
DT40  -  [L05ESDL5V0NA-4_SLP2510P8-10-9]  12.56 70.42 270 top
DV1  -  [BAT54CW_SOT323-3]  70.61 95.22 90 top
DV2  -  [BAT54CW_SOT323-3]  70.45 92.5 90 top
DV3  -  [BAT54CW_SOT323-3]  74.5 93.08 180 top
DV4  -  [AZC199-02SPR7G_SOT23-3]  70.57 104.95 90 top
DV5  -  [PJDLC05C_SOT23-3]  288.85 60.12 90 top
DV6  -  [PJDLC05C_SOT23-3]  288.85 56.18 90 top
DZ1  RB751S40T1G_SOD523-2  [RB520SM-30T2R_EMD2-2]  218 25.78 180 top
DZ2  RB751S40T1G_SOD523-2  [RB520SM-30T2R_EMD2-2]  219.57 27.52 180 top
DZ5  RB751S40T1G_SOD523-2  [RB520SM-30T2R_EMD2-2]  257.36 39.16 270 top
DZ6  RB751S40T1G_SOD523-2  [RB520SM-30T2R_EMD2-2]  263.01 31.2 90 top
DZ7  RB751S40T1G_SOD523-2  [RB520SM-30T2R_EMD2-2]  250.94 12.09 90 top
DZ8  -  [RB751S40T1G_SOD523-2]  253.17 9.25 90 bottom
DZ9  -  [BAT54CW_SOT323-3]  219.54 36.02 0 top
FD1  FIDUCIAL MARK~D  [FIDUCIAL_C40M80]  13.9 11.73 0 top
FD2  FIDUCIAL MARK~D  [FIDUCIAL_C40M80]  291.77 90.19 0 top
FD3  FIDUCIAL MARK~D  [FIDUCIAL_C40M80]  13.9 11.73 180 bottom
FD4  FIDUCIAL MARK~D  [FIDUCIAL_C40M80]  286.95 88.57 180 bottom
H1  -  [H_3P8]  91.15 74.3 0 top
H2  -  [H_3P8]  149.55 74.3 0 top
H3  -  [H_3P8]  91.15 49.8 0 top
H4  -  [H_3P8]  149.55 49.8 0 top
H5  -  [H_1P1N]  101.7 75.86 0 top
H6  -  [H_1P1N]  142.82 52.75 0 top
H7  -  [H_3P2]  243.7 29.25 0 top
H8  -  [H_3P2]  268 74.45 0 top
H9  -  [H_2P8]  283.55 93.6 0 top
H10  H_2P8  [H_2P8-G]  288.05 36.75 0 top
H11  H_2P1X3P6  [H_2P1X3P6-G]  295.3 36.75 90 top
H14  H_4P2X5P2  [H_4P2X5P2-G]  151.05 105.15 270 bottom
H15  H_2P8  [H_2P8-G]  124.55 20.7 0 top
H16  H_3P0  [H_3P0-G]  124.55 13.2 0 top
H17  H_2P8  [H_2P8-G]  38.55 100.6 0 top
H18  H_2P8  [H_2P8-G]  6.15 80.53 0 top
H19  H_2P8  [H_2P8-G]  6.15 62.43 0 top
H20  H_2P8  [H_2P8-G]  15.55 38.05 0 top
H21  H_2P1  [H_2P1-G]  8.85 36.75 0 top
H22  H_2P8  [H_2P8-G]  7.55 12.7 0 top
H23  H_3P0  [H_3P0-G]  21.05 15.3 0 top
H24  H_3P0  [H_3P0-G]  280.05 15.3 180 bottom
H34  -  [H_3P3]  65.55 78.35 180 bottom
H42  -  [H_0P7N]  110.05 107.45 0 top
H43  -  [H_0P9N]  119.25 94.4 0 top
JAPS1  ACES_50506-01841-P01  [ACES_50506-01841-P01_18P]  214.7 14.51 180 bottom
JCRT1  CCM_C070546HR015M29CZR  [CCM_C070546HR015M29CZR_15P-T]  293.9 56.78 90 bottom
JDB1  JXT_FP241AH-006GAAM  [JXT_FP241AH-006GAAM_6P]  25.98 77.52 0 bottom
JDEG1  JXT_FP241AH-010GAAM  [JXT_FP241AH-010GAAM_10P]  237.42 12.97 180 bottom
JDIMM1  LCN_DAN05-Q0406-0103  [LCN_DAN05-Q0406-0103_260P]  50.18 20 180 bottom
JDIMM2  LCN_DAN05-Q0406-0103  [LCN_DAN05-Q0406-0103_260P]  132.17 20 180 bottom
JEDP1  ACES_50398-04041-001  [ACES_50398-04041-001_40P]  68.4 105.35 270 bottom
JESPI  JXT_FP241AH-010GAAM  [JXT_FP241AH-010GAAM_10P]  248.92 34.09 90 bottom
JFAN1  ACES_50271-0040N-001  [ACES_50271-0040N-001_4P]  177.18 87.91 160.2 bottom
JHDMI1  LOTES_AHDM0046-P002A  [LOTES_AHDM0046-P002A_19P-T]  11.05 43.65 90 bottom
JHP1  SINGA_2SJ3095-085111F  [SINGA_2SJ3095-085111F_6P]  288.1 12 90 bottom
JIR1  ACES_50208-0060N-P01  [ACES_50208-0060N-P01_6P]  47.05 97.35 0 bottom
JKBTP1  CVILU_CF5020FD0RK-05-NH  [CVILU_CF5020FD0RK-05-NH_20P-T]  199.15 18.63 0 top
